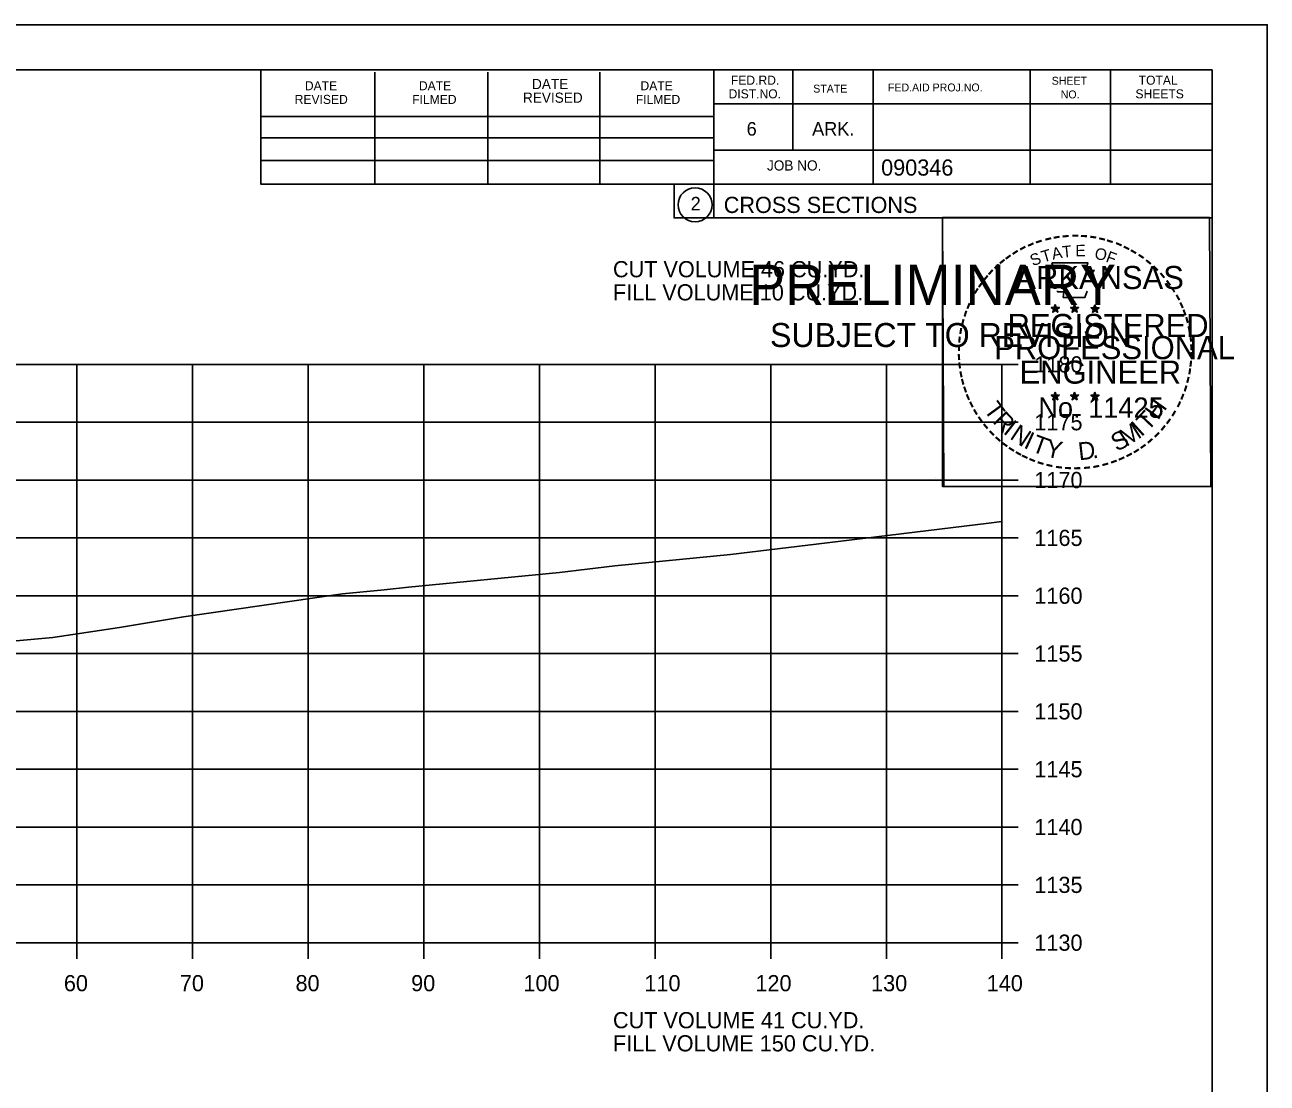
# Model space of a CAD drawing. Extents: x 1368971 to 1374497, y 378717 to 381839.
# Drawn here: x 1369197.1 to 1369304.5, y 380930 to 381021.5 of the extents above; entities that cross this region are included whole.
import ezdxf

# ---------------------------------------------------------------- set-up
doc = ezdxf.new("R2010")
doc.units = 0
for name, color, linetype in [('R_Axis', 7, 'Continuous'), ('R_Axis Annot', 7, 'Continuous'), ('R_Border', 7, 'Continuous'), ('R_Border PE', 7, 'Continuous'), ('R_Border Prem', 7, 'Continuous'), ('R_Exist Surface', 7, 'Continuous'), ('R_Grid', 7, 'Continuous'), ('R_No Plot', 7, 'Continuous')]:
    doc.layers.add(name, color=color, linetype=linetype)

msp = doc.modelspace()

# ---------------------------------------------------------------- linework, layer by layer
at = {"layer": 'R_Axis'}
for p, q in [((1369281.6, 380942.1), (1369281.6, 380992.1)), ((1369283, 380992.1), (1369281.6, 380992.1)), ((1369283, 380987.1), (1369281.6, 380987.1)), ((1369283, 380982.1), (1369281.6, 380982.1)), ((1369283, 380977.1), (1369281.6, 380977.1)), ((1369283, 380972.1), (1369281.6, 380972.1)), ((1369283, 380967.1), (1369281.6, 380967.1)), ((1369283, 380962.1), (1369281.6, 380962.1)), ((1369283, 380957.1), (1369281.6, 380957.1)), ((1369283, 380952.1), (1369281.6, 380952.1)), ((1369283, 380947.1), (1369281.6, 380947.1)), ((1369001.6, 380942.1), (1369281.6, 380942.1)), ((1369201.6, 380940.7), (1369201.6, 380942.1)), ((1369211.6, 380940.7), (1369211.6, 380942.1)), ((1369221.6, 380940.7), (1369221.6, 380942.1)), ((1369231.6, 380940.7), (1369231.6, 380942.1)), ((1369241.6, 380940.7), (1369241.6, 380942.1)), ((1369251.6, 380940.7), (1369251.6, 380942.1)), ((1369261.6, 380940.7), (1369261.6, 380942.1)), ((1369271.6, 380940.7), (1369271.6, 380942.1)), ((1369281.6, 380940.7), (1369281.6, 380942.1)), ((1369283, 380942.1), (1369281.6, 380942.1))]:
    msp.add_line(p, q, dxfattribs=at)
at = {"layer": 'R_Border'}
for p, q in [((1368983.6, 381017.56), (1369299.78, 381017.56)), ((1369217.52, 381007.68), (1369217.52, 381017.56)), ((1369227.38, 381007.68), (1369227.38, 381017.36)), ((1369237.14, 381007.68), (1369237.14, 381017.36)), ((1369246.82, 381007.68), (1369246.82, 381017.36)), ((1369256.68, 381017.56), (1369256.68, 381004.76)), ((1369263.52, 381017.56), (1369263.52, 381010.62)), ((1369270.46, 381017.56), (1369270.46, 381007.68)), ((1369284.04, 381017.56), (1369284.04, 381007.68)), ((1369290.98, 381017.56), (1369290.98, 381007.68)), ((1369299.78, 380812.1), (1369299.78, 381017.56)), ((1369299.78, 381014.62), (1369256.68, 381014.62)), ((1369299.78, 381014.64), (1369299.78, 381014.64)), ((1369217.52, 381013.54), (1369256.68, 381013.54)), ((1369217.52, 381011.68), (1369256.68, 381011.68)), ((1369299.78, 381010.62), (1369256.68, 381010.62)), ((1369259.64, 381010.62), (1369299.78, 381010.62)), ((1369217.52, 381007.68), (1369217.52, 381009.74)), ((1369217.52, 381009.74), (1369256.68, 381009.74)), ((1369299.78, 381007.68), (1369217.52, 381007.68)), ((1369256.68, 381004.76), (1369299.78, 381004.76))]:
    msp.add_line(p, q, dxfattribs=at)
msp.add_circle((1369255.06, 381005.9), 1.47, dxfattribs=at)
at = {"layer": 'R_Border PE'}
for p, q in [((1369285.86, 380997.02), (1369286.21, 380996.91)), ((1369285.86, 380997.02), (1369286.11, 380996.97)), ((1369285.86, 380997.02), (1369286.1, 380996.89)), ((1369285.99, 380996.61), (1369286.21, 380996.91)), ((1369285.99, 380996.61), (1369286.12, 380996.85)), ((1369285.99, 380996.61), (1369286.21, 380996.83)), ((1369286.21, 380997.27), (1369286.17, 380997.02)), ((1369286.21, 380996.91), (1369286.21, 380997.27)), ((1369286.21, 380997.27), (1369286.26, 380997.02)), ((1369286.56, 380997.02), (1369286.21, 380996.91)), ((1369286.42, 380996.61), (1369286.21, 380996.91)), ((1369286.42, 380996.61), (1369286.21, 380996.82)), ((1369286.56, 380997.02), (1369286.27, 380996.97)), ((1369286.42, 380996.61), (1369286.29, 380996.9)), ((1369286.56, 380997.02), (1369286.35, 380996.91)), ((1369287.53, 380997.02), (1369287.88, 380996.91)), ((1369287.53, 380997.02), (1369287.78, 380996.97)), ((1369287.53, 380997.02), (1369287.77, 380996.89)), ((1369287.66, 380996.61), (1369287.88, 380996.91)), ((1369287.66, 380996.61), (1369287.79, 380996.85)), ((1369287.66, 380996.61), (1369287.88, 380996.83)), ((1369287.88, 380997.27), (1369287.84, 380997.02)), ((1369287.88, 380996.91), (1369287.88, 380997.27)), ((1369287.88, 380997.27), (1369287.93, 380997.02)), ((1369288.23, 380997.02), (1369287.88, 380996.91)), ((1369288.09, 380996.61), (1369287.88, 380996.91)), ((1369288.09, 380996.61), (1369287.88, 380996.82)), ((1369288.23, 380997.02), (1369287.94, 380996.97)), ((1369288.09, 380996.61), (1369287.96, 380996.9)), ((1369288.23, 380997.02), (1369288.02, 380996.91)), ((1369289.3, 380997), (1369289.64, 380996.89)), ((1369289.3, 380997), (1369289.55, 380996.96)), ((1369289.3, 380997), (1369289.53, 380996.88)), ((1369289.43, 380996.6), (1369289.64, 380996.89)), ((1369289.43, 380996.6), (1369289.55, 380996.84)), ((1369289.43, 380996.6), (1369289.64, 380996.81)), ((1369289.64, 380997.26), (1369289.6, 380997.01)), ((1369289.64, 380996.89), (1369289.64, 380997.26)), ((1369289.64, 380997.26), (1369289.69, 380997.01)), ((1369289.99, 380997), (1369289.64, 380996.89)), ((1369289.86, 380996.6), (1369289.64, 380996.89)), ((1369289.86, 380996.6), (1369289.64, 380996.81)), ((1369289.99, 380997), (1369289.71, 380996.96)), ((1369289.86, 380996.6), (1369289.72, 380996.89)), ((1369289.99, 380997), (1369289.79, 380996.9)), ((1369285.86, 380989.44), (1369286.21, 380989.33)), ((1369285.86, 380989.44), (1369286.11, 380989.4)), ((1369285.86, 380989.44), (1369286.09, 380989.32)), ((1369285.99, 380989.04), (1369286.21, 380989.33)), ((1369285.99, 380989.04), (1369286.12, 380989.28)), ((1369285.99, 380989.04), (1369286.2, 380989.25)), ((1369286.21, 380989.7), (1369286.17, 380989.45)), ((1369286.42, 380989.04), (1369286.2, 380989.25)), ((1369286.21, 380989.33), (1369286.21, 380989.7)), ((1369286.21, 380989.7), (1369286.26, 380989.45)), ((1369286.55, 380989.44), (1369286.21, 380989.33)), ((1369286.42, 380989.04), (1369286.21, 380989.33)), ((1369286.55, 380989.44), (1369286.27, 380989.39)), ((1369286.42, 380989.04), (1369286.28, 380989.33)), ((1369286.55, 380989.44), (1369286.35, 380989.34)), ((1369287.53, 380989.44), (1369287.88, 380989.33)), ((1369287.53, 380989.44), (1369287.78, 380989.4)), ((1369287.53, 380989.44), (1369287.76, 380989.32)), ((1369287.66, 380989.04), (1369287.88, 380989.33)), ((1369287.66, 380989.04), (1369287.79, 380989.28)), ((1369287.66, 380989.04), (1369287.87, 380989.25)), ((1369287.88, 380989.7), (1369287.83, 380989.45)), ((1369288.09, 380989.04), (1369287.87, 380989.25)), ((1369287.88, 380989.33), (1369287.88, 380989.7)), ((1369287.88, 380989.7), (1369287.92, 380989.45)), ((1369288.22, 380989.44), (1369287.88, 380989.33)), ((1369288.09, 380989.04), (1369287.88, 380989.33)), ((1369288.22, 380989.44), (1369287.94, 380989.39)), ((1369288.09, 380989.04), (1369287.95, 380989.33)), ((1369288.22, 380989.44), (1369288.02, 380989.34)), ((1369289.29, 380989.43), (1369289.64, 380989.32)), ((1369289.29, 380989.43), (1369289.55, 380989.39)), ((1369289.29, 380989.43), (1369289.53, 380989.31)), ((1369289.43, 380989.03), (1369289.64, 380989.32)), ((1369289.43, 380989.03), (1369289.55, 380989.27)), ((1369289.43, 380989.03), (1369289.64, 380989.24)), ((1369289.64, 380989.69), (1369289.6, 380989.44)), ((1369289.64, 380989.32), (1369289.64, 380989.69)), ((1369289.64, 380989.69), (1369289.69, 380989.44)), ((1369289.99, 380989.43), (1369289.64, 380989.32)), ((1369289.86, 380989.03), (1369289.64, 380989.32)), ((1369289.86, 380989.03), (1369289.64, 380989.24)), ((1369289.99, 380989.43), (1369289.7, 380989.38)), ((1369289.86, 380989.03), (1369289.72, 380989.32)), ((1369289.99, 380989.43), (1369289.79, 380989.33))]:
    msp.add_line(p, q, dxfattribs=at)
for points in [[(1369285.9, 381000.89), (1369286.17, 381000.07)], [(1369289.41, 380999.97), (1369289.56, 381000.26), (1369288.87, 381000.23), (1369289.02, 381000.89), (1369285.9, 381000.89)], [(1369286.39, 380998.47), (1369286.39, 380998.38), (1369286.96, 380998.37), (1369286.9, 380997.89), (1369288.77, 380997.89), (1369288.97, 380998.43)], [(1369286.21, 380997.27), (1369286.42, 380996.61), (1369285.86, 380997.02), (1369286.56, 380997.02), (1369285.99, 380996.61), (1369286.21, 380997.27)], [(1369287.88, 380997.27), (1369288.09, 380996.61), (1369287.53, 380997.02), (1369288.23, 380997.02), (1369287.66, 380996.61), (1369287.88, 380997.27)], [(1369289.64, 380997.26), (1369289.86, 380996.6), (1369289.3, 380997), (1369289.99, 380997), (1369289.43, 380996.6), (1369289.64, 380997.26)], [(1369286.21, 380989.7), (1369286.42, 380989.04), (1369285.86, 380989.44), (1369286.55, 380989.44), (1369285.99, 380989.04), (1369286.21, 380989.7)], [(1369287.88, 380989.7), (1369288.09, 380989.04), (1369287.53, 380989.44), (1369288.22, 380989.44), (1369287.66, 380989.04), (1369287.88, 380989.7)], [(1369289.64, 380989.69), (1369289.86, 380989.03), (1369289.29, 380989.43), (1369289.99, 380989.43), (1369289.43, 380989.03), (1369289.64, 380989.69)]]:
    msp.add_lwpolyline(points, dxfattribs=at)
for centre, radius in [((1369286.21, 380996.9), 0.172), ((1369286.21, 380996.9), 0.145), ((1369286.21, 380996.9), 0.116), ((1369286.21, 380996.9), 0.0991), ((1369286.21, 380996.9), 0.0747), ((1369286.21, 380996.9), 0.0495), ((1369286.21, 380996.9), 0.0296), ((1369287.88, 380996.9), 0.172), ((1369287.88, 380996.9), 0.145), ((1369287.88, 380996.9), 0.116), ((1369287.88, 380996.9), 0.0991), ((1369287.88, 380996.9), 0.0747), ((1369287.88, 380996.9), 0.0495), ((1369287.88, 380996.9), 0.0296), ((1369289.64, 380996.89), 0.172), ((1369289.64, 380996.89), 0.145), ((1369289.64, 380996.89), 0.116), ((1369289.64, 380996.89), 0.0991), ((1369289.64, 380996.89), 0.0747), ((1369289.64, 380996.89), 0.0495), ((1369289.64, 380996.89), 0.0296), ((1369286.21, 380989.33), 0.172), ((1369286.21, 380989.33), 0.145), ((1369286.21, 380989.33), 0.116), ((1369286.21, 380989.33), 0.0991), ((1369286.21, 380989.33), 0.0747), ((1369286.21, 380989.33), 0.0495), ((1369286.21, 380989.33), 0.0296), ((1369287.87, 380989.33), 0.172), ((1369287.87, 380989.33), 0.145), ((1369287.87, 380989.33), 0.116), ((1369287.87, 380989.33), 0.0991), ((1369287.87, 380989.33), 0.0747), ((1369287.87, 380989.33), 0.0495), ((1369287.87, 380989.33), 0.0296), ((1369289.64, 380989.32), 0.172), ((1369289.64, 380989.32), 0.145), ((1369289.64, 380989.32), 0.116), ((1369289.64, 380989.32), 0.0991), ((1369289.64, 380989.32), 0.0747), ((1369289.64, 380989.32), 0.0495), ((1369289.64, 380989.32), 0.0296)]:
    msp.add_circle(centre, radius, dxfattribs=at)
at = {"layer": 'R_Exist Surface'}
msp.add_lwpolyline([(1369196.03, 380968.17), (1369199.52, 380968.5), (1369205.29, 380969.36), (1369210.82, 380970.26), (1369224.57, 380972.25), (1369228.17, 380972.61), (1369230.27, 380972.85), (1369243.34, 380974.1), (1369248.11, 380974.67), (1369258.11, 380975.67), (1369266.48, 380976.68), (1369280.46, 380978.37), (1369281.6, 380978.52)], dxfattribs=at)
at = {"layer": 'R_Grid'}
for p, q in [((1369001.6, 380992.1), (1369281.6, 380992.1)), ((1369201.6, 380942.1), (1369201.6, 380992.1)), ((1369211.6, 380942.1), (1369211.6, 380992.1)), ((1369221.6, 380942.1), (1369221.6, 380992.1)), ((1369231.6, 380942.1), (1369231.6, 380992.1)), ((1369241.6, 380942.1), (1369241.6, 380992.1)), ((1369251.6, 380942.1), (1369251.6, 380992.1)), ((1369261.6, 380942.1), (1369261.6, 380992.1)), ((1369271.6, 380942.1), (1369271.6, 380992.1)), ((1369281.6, 380942.1), (1369281.6, 380992.1)), ((1369001.6, 380987.1), (1369281.6, 380987.1)), ((1369001.6, 380982.1), (1369281.6, 380982.1)), ((1369001.6, 380977.1), (1369281.6, 380977.1)), ((1369001.6, 380972.1), (1369281.6, 380972.1)), ((1369001.6, 380967.1), (1369281.6, 380967.1)), ((1369001.6, 380962.1), (1369281.6, 380962.1)), ((1369001.6, 380957.1), (1369281.6, 380957.1)), ((1369001.6, 380952.1), (1369281.6, 380952.1)), ((1369001.6, 380947.1), (1369281.6, 380947.1)), ((1369001.6, 380942.1), (1369281.6, 380942.1))]:
    msp.add_line(p, q, dxfattribs=at)
at = {"layer": 'R_No Plot'}
for p, q in [((1368971.2, 381021.46), (1369304.53, 381021.46)), ((1369275.81, 380982.31), (1369275.81, 380982.31))]:
    msp.add_line(p, q, dxfattribs=at)
for points in [[(1368971.19, 381021.46), (1369304.53, 381021.46), (1369304.53, 380808.12), (1368971.19, 380808.12)], [(1369217.52, 381017.56), (1369217.52, 381007.68), (1369253.25, 381007.68), (1369253.25, 381004.76), (1369276.45, 381004.76), (1369276.45, 380981.55), (1369299.78, 380981.55), (1369299.78, 380812.1), (1368983.6, 380812.1), (1368983.6, 381017.56)], [(1369276.45, 381004.79), (1369299.55, 381004.79), (1369299.66, 380981.55), (1369276.56, 380981.55)]]:
    msp.add_lwpolyline(points, close=True, dxfattribs=at)

# ---------------------------------------------------------------- texts
at = {"layer": 'R_Axis Annot'}
for s, p in [('CUT VOLUME 46 CU.YD.', (1369247.96, 380999.63)), ('FILL VOLUME 10 CU.YD.', (1369247.96, 380997.63)), ('1180', (1369284.4, 380991.4)), ('1175', (1369284.4, 380986.4)), ('1170', (1369284.4, 380981.4)), ('1165', (1369284.4, 380976.4)), ('1160', (1369284.4, 380971.4)), ('1155', (1369284.4, 380966.4)), ('1150', (1369284.4, 380961.4)), ('1145', (1369284.4, 380956.4)), ('1140', (1369284.4, 380951.4)), ('1135', (1369284.4, 380946.4)), ('1130', (1369284.4, 380941.4)), ('60', (1369200.48, 380937.9)), ('70', (1369210.51, 380937.9)), ('80', (1369220.51, 380937.9)), ('90', (1369230.51, 380937.9)), ('100', (1369240.22, 380937.9)), ('110', (1369250.68, 380937.9)), ('120', (1369260.28, 380937.9)), ('130', (1369270.28, 380937.9)), ('140', (1369280.28, 380937.9)), ('CUT VOLUME 41 CU.YD.', (1369247.96, 380934.7)), ('FILL VOLUME 150 CU.YD.', (1369247.96, 380932.7))]:
    msp.add_text(s, height=1.4, dxfattribs=at).set_placement(p)
at = {"layer": 'R_Border'}
for s, height, p in [('FED.RD.', 0.782, (1369258.16, 381016.28)), ('SHEET', 0.684, (1369285.9, 381016.28)), ('TOTAL', 0.782, (1369293.42, 381016.28)), ('DATE', 0.782, (1369221.32, 381015.8)), ('DATE', 0.782, (1369231.18, 381015.8)), ('DATE', 0.879, (1369240.96, 381015.9)), ('DATE', 0.782, (1369250.34, 381015.8)), ('DIST.NO.', 0.782, (1369257.96, 381015.1)), ('STATE', 0.684, (1369265.28, 381015.6)), ('FED.AID PROJ.NO.', 0.684, (1369271.74, 381015.7)), ('SHEETS', 0.782, (1369293.14, 381015.1)), ('REVISED', 0.782, (1369220.44, 381014.62)), ('FILMED', 0.782, (1369230.6, 381014.62)), ('REVISED', 0.879, (1369240.18, 381014.72)), ('FILMED', 0.782, (1369249.94, 381014.62)), ('NO.', 0.684, (1369286.68, 381015.1)), ('6', 1.17, (1369259.52, 381011.88)), ('ARK.', 1.172, (1369265.18, 381011.88)), ('JOB NO.', 0.879, (1369261.28, 381008.86)), ('2', 1.17, (1369254.68, 381005.41)), ('CROSS SECTIONS', 1.4, (1369257.54, 381005.19))]:
    msp.add_text(s, height=height, dxfattribs=at).set_placement(p)
msp.add_text('090346', height=1.4, rotation=360, dxfattribs=at).set_placement((1369271.15, 381008.42))
at = {"layer": 'R_Border PE'}
for s, height, rotation, p in [('-', 1.6, 13.6301, (1369285.4, 381002.26)), ('-', 1.6, 10.2193, (1369286.08, 381002.42)), ('-', 1.6, 5.8968, (1369286.81, 381002.53)), ('-', 1.6, 0.1862, (1369287.58, 381002.61)), ('-', 1.6, 357.743, (1369288.3, 381002.59)), ('-', 1.6, 352.1617, (1369289.05, 381002.54)), ('-', 1.6, 347.2049, (1369289.77, 381002.42)), ('-', 1.6, 342.3362, (1369290.4, 381002.27)), ('-', 1.6, 34.0636, (1369282.79, 381001.07)), ('-', 1.6, 28.7918, (1369283.38, 381001.44)), ('-', 1.6, 24.3072, (1369284.02, 381001.75)), ('-', 1.6, 19.1761, (1369284.65, 381002.02)), ('T', 1, 16.4036, (1369285.17, 381000.9)), ('A', 1, 11.2132, (1369286, 381001.15)), ('T', 1, 6.0228, (1369286.85, 381001.32)), ('E', 1, 0.8323, (1369287.95, 381001.43)), ('O', 1, 350.4515, (1369289.56, 381001.22)), ('F', 1, 340.0707, (1369290.51, 381000.99)), ('-', 1.6, 337.8551, (1369291.14, 381002.05)), ('-', 1.6, 334.1211, (1369291.77, 381001.77)), ('-', 1.6, 329.6409, (1369292.35, 381001.49)), ('-', 1.6, 42.9622, (1369281.3, 380999.88)), ('-', 1.6, 38.9507, (1369281.73, 381000.29)), ('-', 1.6, 36.2317, (1369282.21, 381000.67)), ('S', 1, 21.594, (1369284.26, 381000.57)), ('-', 1.6, 325.8627, (1369292.99, 381001.13)), ('-', 1.6, 320.5297, (1369293.6, 381000.7)), ('-', 1.6, 50.6142, (1369280.45, 380998.91)), ('-', 1.6, 48.423, (1369280.85, 380999.4)), ('-', 1.6, 315.5786, (1369294.2, 381000.22)), ('-', 1.6, 309.8797, (1369294.77, 380999.67)), ('-', 1.6, 58.0706, (1369279.71, 380997.82)), ('-', 1.6, 54.2325, (1369280.04, 380998.34)), ('-', 1.6, 306.6522, (1369295.29, 380999.06)), ('-', 1.4, 303.6753, (1369295.78, 380998.5)), ('-', 1.6, 62.8713, (1369279.4, 380997.2)), ('-', 1.6, 299.6684, (1369296.1, 380997.89)), ('-', 1.6, 72.3945, (1369278.92, 380995.96)), ('-', 1.6, 67.7743, (1369279.14, 380996.59)), ('-', 1.6, 294.6628, (1369296.42, 380997.28)), ('-', 1.6, 290.5728, (1369296.68, 380996.7)), ('-', 1.6, 75.461, (1369278.72, 380995.25)), ('-', 1.6, 285.1233, (1369296.91, 380996.12)), ('-', 1.6, 280.5493, (1369297.11, 380995.38)), ('-', 1.6, 85.1863, (1369278.51, 380993.84)), ('-', 1.6, 81.2013, (1369278.59, 380994.54)), ('-', 1.6, 276.5962, (1369297.27, 380994.61)), ('-', 1.6, 89.0622, (1369278.49, 380993.14)), ('-', 1.6, 274.3301, (1369297.33, 380993.89)), ('-', 1.6, 94.1959, (1369278.52, 380992.42)), ('-', 1.6, 98.9479, (1369278.6, 380991.75)), ('-', 1.6, 263.5172, (1369297.35, 380992.59)), ('-', 1.6, 269.9407, (1369297.37, 380993.26)), ('-', 1.6, 101.7149, (1369278.73, 380991.02)), ('-', 1.6, 260.9953, (1369297.28, 380991.94)), ('-', 1.6, 105.4578, (1369278.89, 380990.42)), ('-', 1.6, 109.0874, (1369279.11, 380989.79)), ('-', 1.6, 252.8681, (1369296.99, 380990.54)), ('-', 1.6, 255.7626, (1369297.17, 380991.26)), ('-', 1.6, 114.0643, (1369279.36, 380989.2)), ('T', 1.54, 306.0406, (1369279.97, 380988.17)), ('H', 1.54, 54.6088, (1369295.09, 380987.21)), ('-', 1.6, 247.8887, (1369296.76, 380989.87)), ('-', 1.6, 115.7288, (1369279.67, 380988.58)), ('-', 1.6, 120.4471, (1369280.02, 380987.99)), ('R', 1.54, 314.005, (1369280.73, 380987.12)), ('T', 1.54, 46.6444, (1369294.2, 380986.26)), ('-', 1.6, 239.0712, (1369296.11, 380988.48)), ('-', 1.6, 244.6197, (1369296.5, 380989.24)), ('-', 1.6, 125.8934, (1369280.43, 380987.43)), ('-', 1.6, 130.7181, (1369280.89, 380986.88)), ('I', 1.54, 321.9694, (1369281.63, 380986.19)), ('N', 1.54, 326.5002, (1369282.2, 380985.72)), ('M', 1.54, 32.6563, (1369292.35, 380984.94)), ('I', 1.54, 42.1136, (1369293.63, 380985.79)), ('-', 1.6, 231.2538, (1369295.28, 380987.27)), ('-', 1.6, 233.8452, (1369295.71, 380987.83)), ('-', 1.6, 134.2238, (1369281.41, 380986.33)), ('-', 1.6, 138.9338, (1369281.93, 380985.87)), ('I', 1.54, 335.3603, (1369283.4, 380984.93)), ('T', 1.54, 339.8912, (1369284.07, 380984.61)), ('S', 1.54, 26.9312, (1369291.51, 380984.53)), ('-', 1.6, 221.0851, (1369294.27, 380986.19)), ('-', 1.6, 225.7653, (1369294.8, 380986.7)), ('-', 1.6, 144.6463, (1369282.49, 380985.46)), ('-', 1.6, 148.0898, (1369283.05, 380985.09)), ('Y', 1.54, 347.8556, (1369285.28, 380984.16)), ('D', 1.54, 6.3969, (1369288.27, 380983.8)), ('-', 1.6, 212.2491, (1369293.19, 380985.33)), ('-', 1.6, 215.7363, (1369293.73, 380985.72)), ('-', 1.6, 151.5704, (1369283.63, 380984.77)), ('-', 1.6, 154.6002, (1369284.15, 380984.52)), ('-', 1.6, 158.5612, (1369284.77, 380984.27)), ('-', 1.6, 162.7983, (1369285.46, 380984.05)), ('.', 1.54, 13.7642, (1369289.46, 380983.93)), ('-', 1.6, 195.4743, (1369290.71, 380984.15)), ('-', 1.6, 200.7184, (1369291.39, 380984.4)), ('-', 1.6, 204.2516, (1369292.01, 380984.67)), ('-', 1.6, 207.3568, (1369292.63, 380984.99)), ('-', 1.6, 167.5555, (1369286.18, 380983.89)), ('-', 1.6, 173.1155, (1369286.95, 380983.78)), ('-', 1.6, 176.5183, (1369287.7, 380983.73)), ('-', 1.6, 181.5918, (1369288.44, 380983.75)), ('-', 1.6, 185.8167, (1369289.25, 380983.82)), ('-', 1.6, 191.2858, (1369289.98, 380983.95))]:
    msp.add_text(s, height=height, rotation=rotation, dxfattribs=at).set_placement(p)
for s, height, p in [('ARKANSAS', 2, (1369282.76, 380998.61)), ('REGISTERED', 2, (1369282.08, 380994.46)), ('DWB', 0.01, (1369286.2, 380996.9)), ('DWB', 0.01, (1369287.87, 380996.9)), ('DWB', 0.01, (1369289.63, 380996.89)), ('PROFESSIONAL', 2, (1369280.93, 380992.55)), ('ENGINEER', 2, (1369283.12, 380990.43)), ('No. 11425', 1.757, (1369284.74, 380987.48)), ('DWB', 0.01, (1369286.19, 380989.33)), ('DWB', 0.01, (1369287.86, 380989.33)), ('DWB', 0.01, (1369289.63, 380989.32))]:
    msp.add_text(s, height=height, dxfattribs=at).set_placement(p)
at = {"layer": 'R_Border Prem'}
for s, height, p in [('PRELIMINARY', 3.5, (1369259.73, 380997.22)), ('DWB', 0.01, (1369260.47, 380999.07)), ('SUBJECT TO REVISION', 2.0751, (1369261.54, 380993.6))]:
    msp.add_text(s, height=height, dxfattribs=at).set_placement(p)

doc.saveas('drawing.dxf')
